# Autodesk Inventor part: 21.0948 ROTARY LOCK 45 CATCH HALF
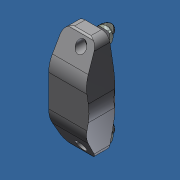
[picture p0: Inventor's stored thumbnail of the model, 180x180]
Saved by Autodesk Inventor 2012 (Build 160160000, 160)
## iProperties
Created: 2014-05
Part Number: 21.0948 ROTARY LOCK 45 CATCH HALF
Material: Aluminum-6061
Document SubType Name: Modeling
Designer: Admin
Density: 2.71 g/cm^3
Mass: 132.881 g
Surface Area: 217.573 cm^2
Volume: 49.0337 cm^3
Art.-Nr.: 21.0948/0
L: -
Stück: 1
5: Drehriegelschloß
7: 21.0948/0
8: MiniTec Maschinenbau GmbH & Co KG
Author: Admin
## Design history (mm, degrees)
feature "Alias Freeform"
body "Solid1"
